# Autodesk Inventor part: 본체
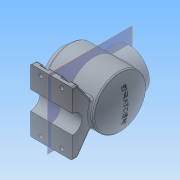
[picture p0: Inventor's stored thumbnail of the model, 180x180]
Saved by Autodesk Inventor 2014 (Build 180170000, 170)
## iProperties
Created: 2017-04
Part Number: 본체
Material: 일반
Document SubType Name: Modeling
Designer: NET
Density: 1 g/cm^3
Appearance: 기본값
Mass: 616.468 g
Surface Area: 1066.88 cm^2
Volume: 616.468 cm^3
Author: NET
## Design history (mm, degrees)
sketch "스케치1"
  geometry: L1 (0, 0)-(0, 50); L2 (0, 50)-(96.336, 50); L3 (0, 0)-(108, 0); L4 (89.916, 40)-(10, 40); L5 (10, 40)-(10, 0); A1 r 113 centre (-5, 0) between (108, 0) and (96.336, 50); A2 r 103 centre (-5, 0) between (98, 0) and (89.916, 40)
  constraints: 10 end point, 4 point on circle, 2 centre point, 2 parallel, 2 point on line, 1 horizontal, 1 vertical
  dimensions: "d8" = 100 diameter of L2 L3; "d16" = 108 distance edge to line of A1 L1; "d19" = 108 distance of L1.start L3.end; "d21" = 5 distance from line of L1 A1.centre; "d22" = 10 radial gap between concentric circles of A2 A1; "d23" = 40 distance of L4.end L5.end; "d24" = 79.91575 distance of L4.start L4.end
revolve "회전1" stored, may be unused: angle "d25" = 90 deg
node "작업 평면1"
sketch "스케치2"
  geometry: L1 (0, 50)-(0, -50) reference; C1 r 38 at (-50, 0); 3 further points
  constraints: 1 centre point, 1 coincident, 1 horizontal alignment, 1 midpoint
  dimensions: "d28" = 50 distance of point (0, 0) point (-50, 0); "d29" = 76 diameter of C1
extrude "돌출1" join sketch "스케치2" stored distance "d30" = 10; taper "d31" = 0 deg
sketch "스케치3"
  geometry: C1 r 50 at (0, 0) reference; C2 r 38 at (0, 0)
  constraints: 1 centre point, 1 coincident
  dimensions: "d32" = 76 diameter of C2
extrude "돌출2" join sketch "스케치3" distance "d33" = 12; taper "d34" = 0 deg
node "작업 평면2"
sketch "스케치4"
  geometry: L1 (-88.168, -60)-(-8.168, -60); L2 (-8.168, -60)-(-8.168, 60); L3 (-8.168, 60)-(-88.168, 60); L4 (-88.168, 60)-(-88.168, -60); L5 (0, -50)-(-96.336, -50) reference; L6 (-96.336, 50)-(-96.336, -50) reference; 4 further points
  constraints: 8 end point, 4 midpoint, 4 parallel, 1 horizontal alignment, 1 vertical alignment
  dimensions: "d38" = 120 distance of L3.end L1.start; "d39" = 80 distance of L2.end L3.end
extrude "돌출3" join sketch "스케치4" distance "d40" = 10; taper "d41" = 0 deg
node "작업 평면3"
sketch "스케치5"
  geometry: L1 (0, 0)-(120, 0) reference; L2 (120, 0)-(120, 10) reference; L3 (0, 10)-(120, 10) reference; L4 (0, 0)-(0, 10) reference; L5 (120, 10)-(81.584, 36.899); L6 (0, 10)-(38.416, 36.899); A1 r 50 centre (60, 82) between (81.584, 36.899) and (38.416, 36.899) reference; 1 further point
  constraints: 4 end point, 2 point on circle
  dimensions: "d43" = 55 deg angle of L4 L6; "d44" = 55 deg angle of L2 L5
extrude "돌출4" join sketch "스케치5" stored distance "d45" = 80; taper "d46" = 0 deg
sketch "스케치6"
  geometry: L1 (0, 0)-(120, 0) reference; C1 r 18 at (60, 0)
  constraints: 1 centre point, 1 midpoint
  dimensions: "d47" = 36 diameter of C1
extrude "돌출5" cut sketch "스케치6" stored distance "d48" = 80; taper "d49" = 0 deg
fillet "모깎기1" dims "d50" = 3
fillet "모깎기2" dims "d51" = 3
revolve "회전2" stored, may be unused: angle "d52" = 90 deg
sketch "스케치7"
  geometry: C1 r 38 at (0, 0) reference; C2 r 27 at (0, 0)
  constraints: 1 centre point, 1 coincident
  dimensions: "d53" = 54 diameter of C2
extrude "돌출6" cut sketch "스케치7" distance "d54" = 22; taper "d55" = 0 deg
sketch "스케치8"
  geometry: C1 r 38 at (0, 0) reference; C2 r 27 at (0, 0); 1 further point
  constraints: 1 centre point, 1 coincident
  dimensions: "d56" = 54 diameter of C2
extrude "돌출7" cut sketch "스케치8" stored distance "d57" = 30; taper "d58" = 0 deg
sketch "스케치9"
  geometry: L1 (77, 0)-(77, 43.617) reference; L2 (0, 0)-(0, 40.47) reference; L3 (0, -2.457)-(74, -2.457) reference; L4 (49, 7.543)-(49, -2.457); L5 (65, 7.543)-(65, -2.457); L6 (49, -2.457)-(65, -2.457); A1 r 8 centre (57, 7.543) between (49, 7.543) and (65, 7.543); 1 further point
  constraints: 6 end point, 2 point on circle, 2 point on line, 2 tangent, 1 centre point, 1 parallel, 1 vertical
  dimensions: "d79" = 16 diameter of A1; "d80" = 10 distance from line of L3 A1.centre; "d81" = 20 distance from line of A1.centre L1
node "작업 평면4"
node "작업 평면5"
sketch "스케치14" dims "d88" = 65
  geometry: C1 r 27 at (0, 0) reference; C2 r 38 at (0, 0) reference; 3 further points
  constraints: 2 vertical alignment, 1 coincident, 2 other
hole "구멍1" sketch "스케치14" at (0, 32.5) diameter "d89" = 3.242; stored, may be unused: countersink angle "d93" = 90 deg, drill point angle "d95" = 118 deg; dims "d90" = 8, "d91" = 16, "d92" = 6, "d94" = 10
sketch "스케치15" dims "d99" = 65
  geometry: C1 r 38 at (0, 0) reference; 2 further points
  constraints: 2 vertical alignment, 1 coincident, 2 other
hole "구멍2" sketch "스케치15" at (0, 32.5) diameter "d100" = 3.242; stored, may be unused: countersink angle "d104" = 90 deg, drill point angle "d106" = 118 deg; dims "d101" = 8, "d102" = 16, "d103" = 6, "d105" = 10
node "작업 평면6"
sketch "스케치16"
  geometry: 2 further points
  constraints: 1 coincident, 1 other
feature "엠보싱1" sketch "스케치16" dims "d110" = 0.5, "d111" = 0
fillet "모깎기3" dims "d115" = 3
fillet "모깎기4" dims "d116" = 3
chamfer "모따기1" distance "d117" = 1; stored, may be unused: second distance "d118" = 2, angle "d119" = 45 deg
chamfer "모따기2" distance "d120" = 1; stored, may be unused: second distance "d121" = 2, angle "d122" = 45 deg
fillet "모깎기5" dims "d123" = 3
sketch "스케치17"
  geometry: L1 (11.168, 60)-(85.168, 60) reference; L2 (8.168, 18)-(8.168, 57) reference; C1 r 4 at (28.168, 50); 1 further point
  constraints: 1 centre point
  dimensions: "d124" = 20 distance from line of C1.centre L2; "d125" = 10 distance from line of C1.centre L1; "d128" = 8 diameter of C1
extrude "돌출14" cut sketch "스케치17" distance "d126" = 6; taper "d127" = 0 deg
sketch "스케치18"
  geometry: L1 (-8, 0)-(-8, 10); L2 (8, 0)-(8, 10); L3 (8, 10)-(-8, 10); L4 (-17, 10)-(57, 10) reference; C1 r 4 at (0, 0) reference; A1 r 8 centre (0, 0) between (-8, 0) and (8, 0); 1 further point
  constraints: 6 end point, 2 point on circle, 2 tangent, 1 centre point, 1 coincident, 1 collinear, 1 parallel, 1 vertical
  dimensions: "d129" = 16 diameter of A1
extrude "돌출15" cut sketch "스케치18" stored distance "d130" = 6; taper "d131" = 0 deg
sketch "스케치19"
  geometry: C1 r 4 at (0, 0) reference; C2 r 4 at (0, 0); 1 further point
  constraints: 1 centre point, 1 coincident
  dimensions: "d132" = 8 diameter of C2
extrude "돌출16" cut sketch "스케치19" stored distance "d133" = 6; taper "d134" = 0 deg
sketch "스케치20"
  geometry: C1 r 4 at (0, 0) reference; C2 r 4 at (0, 0); 1 further point
  constraints: 1 centre point, 1 coincident
  dimensions: "d135" = 8 diameter of C2
extrude "돌출17" cut sketch "스케치20" stored distance "d136" = 6; taper "d137" = 0 deg
sketch "스케치21"
  geometry: C1 r 4 at (0, 0) reference; C2 r 4 at (0, 0); 1 further point
  constraints: 1 centre point, 1 coincident
  dimensions: "d138" = 8 diameter of C2
extrude "돌출18" cut sketch "스케치21" stored distance "d139" = 6; taper "d140" = 0 deg
sketch "스케치22"
  geometry: C1 r 4 at (0, 0) reference; C2 r 4 at (0, 0); 1 further point
  constraints: 1 centre point, 1 coincident
  dimensions: "d141" = 8 diameter of C2
extrude "돌출19" cut sketch "스케치22" stored distance "d142" = 6; taper "d143" = 0 deg
sketch "스케치11"
  geometry: C1 r 4 at (4.581, 8.007); 4 further points; 1 other entity
  constraints: 1 centre point, 1 coincident, 1 other
  dimensions: "d74" = 8 diameter of C1
extrude "돌출10" cut sketch "스케치11" stored distance "d75" = 12; taper "d76" = 0 deg
sketch "스케치12"
  geometry: L1 (74, -40.47)-(0, -40.47) reference; L2 (74, 0)-(74, -40.47) reference; L3 (0, 0)-(74, 0) reference; L4 (0, -40.47)-(0, 0) reference; L5 (74, -40.47)-(0, -40.47) reference; A1 r 8 centre (57, -37.768) between (64.53, -40.47) and (49.47, -40.47) reference; 1 further point
extrude "돌출11" cut sketch "스케치9" stored distance "d77" = 12; taper "d78" = 0 deg
sketch "스케치10"
  geometry: L1 (11.168, 60)-(85.168, 60) reference; L2 (88.168, 57)-(88.168, 18) reference; C1 r 4 at (68.168, 50); 1 further point
  constraints: 1 centre point
  dimensions: "d63" = 8 diameter of C1; "d64" = 20 distance from line of L2 C1.centre; "d65" = 10 distance from line of L1 C1.centre
extrude "돌출8" cut sketch "스케치10" distance "d66" = 6; taper "d67" = 0 deg
node "솔리드1"
pattern_circular "원형 패턴1" dims angle "d97" = 360 deg
pattern_circular "원형 패턴2" dims angle "d108" = 360 deg
mirror "대칭3"
mirror "대칭4"
node "투영된 루프1"
node "투영된 루프2"
other parameters: "d26" = 65, "d35" = -82, "d71" = -6
